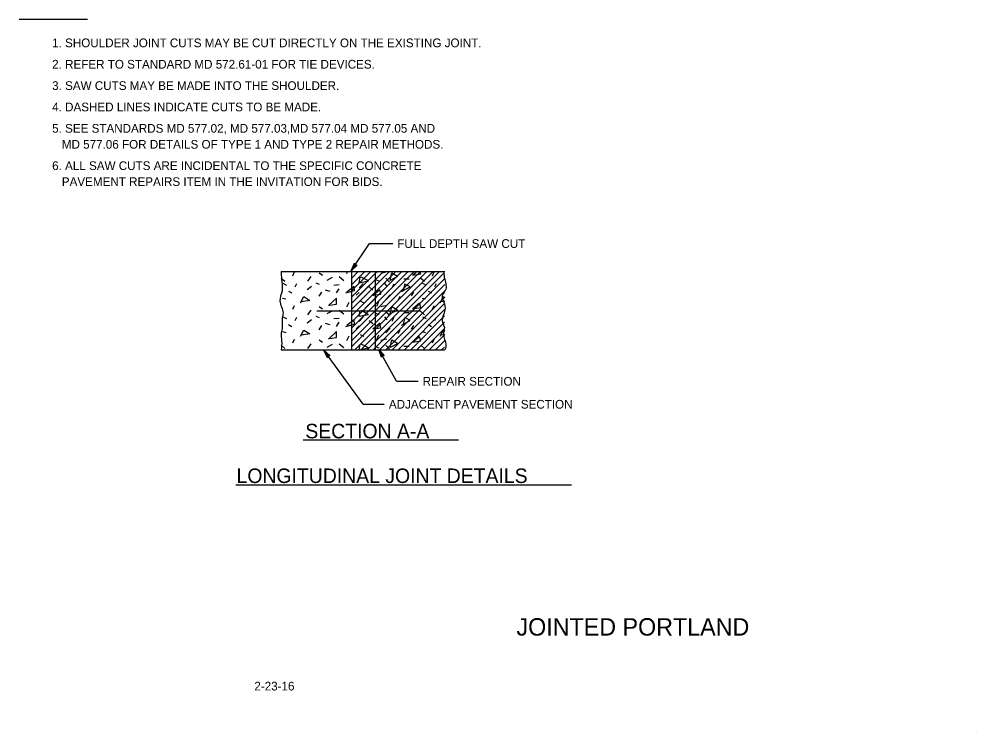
# Model space of a CAD drawing. Extents: x 1.45 to 8.06, y 0.17 to 9.98.
# Drawn here: x 1.45 to 8.06, y 0.17 to 5.09 of the extents above; entities that cross this region are included whole.
import ezdxf

# ---------------------------------------------------------------- set-up
doc = ezdxf.new("R2010")
doc.units = 0
for name, color, linetype in [('DETL-DIMS', 7, 'Continuous'), ('DETL-LINE', 7, 'Continuous'), ('DETL-NOTE', 7, 'Continuous'), ('DETL-PATT', 7, 'Continuous'), ('DETL-TITL', 7, 'Continuous'), ('TTLB-TEXT', 7, 'Continuous')]:
    doc.layers.add(name, color=color, linetype=linetype)

msp = doc.modelspace()

# ---------------------------------------------------------------- linework, layer by layer
at = {"layer": 'DETL-DIMS'}
for p, q in [((3.7436, 3.3526), (3.8699, 3.5416)), ((3.8699, 3.5416), (4.0305, 3.5416)), ((3.9662, 3.5416), (4.0305, 3.5416)), ((3.8267, 2.4338), (3.5558, 2.8069)), ((3.8267, 2.4338), (3.5558, 2.8069)), ((4.0547, 2.5922), (3.934, 2.8122)), ((4.0547, 2.5922), (3.934, 2.8122)), ((4.0547, 2.5922), (4.2054, 2.5922)), ((3.8267, 2.4338), (3.9713, 2.4338))]:
    msp.add_line(p, q, dxfattribs=at)
for points in [[(3.7436, 3.3526), (3.7662, 3.4054), (3.7663, 3.4001), (3.7682, 3.3962), (3.771, 3.3935), (3.7745, 3.392), (3.7789, 3.3917), (3.7838, 3.3937), (3.7436, 3.3526), (3.7789, 3.3917), (3.7745, 3.392), (3.7436, 3.3526), (3.771, 3.3935), (3.7682, 3.3962), (3.7436, 3.3526), (3.7663, 3.4001)], [(3.5558, 2.8069), (3.5975, 2.7674), (3.5925, 2.7691), (3.5882, 2.7687), (3.5847, 2.767), (3.582, 2.7643), (3.5803, 2.7602), (3.5804, 2.7549), (3.5558, 2.8069), (3.5803, 2.7602), (3.582, 2.7643), (3.5558, 2.8069), (3.5847, 2.767), (3.5882, 2.7687), (3.5558, 2.8069), (3.5925, 2.7691)], [(3.5558, 2.8069), (3.5975, 2.7674), (3.5925, 2.7691), (3.5882, 2.7687), (3.5847, 2.767), (3.582, 2.7643), (3.5803, 2.7602), (3.5804, 2.7549), (3.5558, 2.8069), (3.5803, 2.7602), (3.582, 2.7643), (3.5558, 2.8069), (3.5847, 2.767), (3.5882, 2.7687), (3.5558, 2.8069), (3.5925, 2.7691)], [(3.5558, 2.8069), (3.5975, 2.7674), (3.5925, 2.7691), (3.5882, 2.7687), (3.5847, 2.767), (3.582, 2.7643), (3.5803, 2.7602), (3.5804, 2.7549), (3.5558, 2.8069), (3.5803, 2.7602), (3.582, 2.7643), (3.5558, 2.8069), (3.5847, 2.767), (3.5882, 2.7687), (3.5558, 2.8069), (3.5925, 2.7691)], [(3.5558, 2.8069), (3.5975, 2.7674), (3.5925, 2.7691), (3.5882, 2.7687), (3.5847, 2.767), (3.582, 2.7643), (3.5803, 2.7602), (3.5804, 2.7549), (3.5558, 2.8069), (3.5803, 2.7602), (3.582, 2.7643), (3.5558, 2.8069), (3.5847, 2.767), (3.5882, 2.7687), (3.5558, 2.8069), (3.5925, 2.7691)], [(3.5558, 2.8069), (3.5975, 2.7674), (3.5925, 2.7691), (3.5882, 2.7687), (3.5847, 2.767), (3.582, 2.7643), (3.5803, 2.7602), (3.5804, 2.7549), (3.5558, 2.8069), (3.5803, 2.7602), (3.582, 2.7643), (3.5558, 2.8069), (3.5847, 2.767), (3.5882, 2.7687), (3.5558, 2.8069), (3.5925, 2.7691)], [(3.934, 2.8122), (3.9704, 2.7678), (3.9657, 2.7702), (3.9613, 2.7703), (3.9577, 2.7691), (3.9547, 2.7667), (3.9524, 2.7629), (3.9519, 2.7576), (3.934, 2.8122), (3.9524, 2.7629), (3.9547, 2.7667), (3.934, 2.8122), (3.9577, 2.7691), (3.9613, 2.7703), (3.934, 2.8122), (3.9657, 2.7702)], [(3.934, 2.8122), (3.9704, 2.7678), (3.9657, 2.7702), (3.9613, 2.7703), (3.9577, 2.7691), (3.9547, 2.7667), (3.9524, 2.7629), (3.9519, 2.7576), (3.934, 2.8122), (3.9524, 2.7629), (3.9547, 2.7667), (3.934, 2.8122), (3.9577, 2.7691), (3.9613, 2.7703), (3.934, 2.8122), (3.9657, 2.7702)], [(3.934, 2.8122), (3.9704, 2.7678), (3.9657, 2.7702), (3.9613, 2.7703), (3.9577, 2.7691), (3.9547, 2.7667), (3.9524, 2.7629), (3.9519, 2.7576), (3.934, 2.8122), (3.9524, 2.7629), (3.9547, 2.7667), (3.934, 2.8122), (3.9577, 2.7691), (3.9613, 2.7703), (3.934, 2.8122), (3.9657, 2.7702)], [(3.934, 2.8122), (3.9704, 2.7678), (3.9657, 2.7702), (3.9613, 2.7703), (3.9577, 2.7691), (3.9547, 2.7667), (3.9524, 2.7629), (3.9519, 2.7576), (3.934, 2.8122), (3.9524, 2.7629), (3.9547, 2.7667), (3.934, 2.8122), (3.9577, 2.7691), (3.9613, 2.7703), (3.934, 2.8122), (3.9657, 2.7702)]]:
    msp.add_lwpolyline(points, dxfattribs=at)
at = {"layer": 'DETL-LINE'}
for p, q in [((3.2601, 3.3482), (4.38, 3.3482)), ((3.7447, 3.3471), (3.7447, 3.0778)), ((3.9082, 3.3482), (3.9082, 2.8084)), ((3.5059, 3.0778), (4.2241, 3.0778)), ((3.5059, 3.0778), (4.2241, 3.0778)), ((3.7447, 3.0778), (3.7447, 2.8084)), ((3.2601, 2.8084), (4.3638, 2.8084)), ((3.2601, 2.8084), (4.3638, 2.8084)), ((4.3552, 2.8084), (4.3898, 2.8084))]:
    msp.add_line(p, q, dxfattribs=at)
for points in [[(3.2601, 3.3482), (3.2639, 3.2962), (3.2666, 3.2165), (3.2517, 3.1462), (3.2733, 3.0638), (3.2679, 3.03), (3.2679, 2.9638), (3.2612, 2.926), (3.2639, 2.8706), (3.2601, 2.8084)], [(4.38, 3.3482), (4.3878, 3.2949), (4.3921, 3.2173), (4.3706, 3.1806), (4.3813, 3.1374), (4.39, 3.0814), (4.3706, 3.0123), (4.3857, 2.9627), (4.3792, 2.9152), (4.3964, 2.8462), (4.3898, 2.8084)]]:
    msp.add_spline(points, degree=3, dxfattribs=at)
at = {"layer": 'DETL-NOTE'}
msp.add_line((1.4545, 5.0884), (1.9256, 5.0884), dxfattribs=at)
at = {"layer": 'DETL-PATT'}
for p, q in [((3.2601, 3.3039), (3.2856, 3.2815)), ((3.3402, 3.32), (3.353, 3.3457)), ((3.4653, 3.3136), (3.4429, 3.2815)), ((3.5231, 3.3393), (3.5456, 3.3233)), ((3.613, 3.3072), (3.5745, 3.288)), ((3.6611, 3.3136), (3.6932, 3.288)), ((3.7125, 3.3361), (3.7185, 3.3482)), ((3.7439, 2.8283), (4.2611, 3.3455)), ((3.7439, 2.8283), (4.2611, 3.3455)), ((3.7447, 3.1719), (3.9201, 3.3473)), ((3.7447, 3.1291), (3.9627, 3.3471)), ((3.7447, 3.0862), (4.0053, 3.3468)), ((3.7447, 3.0433), (4.0479, 3.3466)), ((3.7447, 3.0005), (4.0906, 3.3464)), ((3.7447, 2.9576), (4.1332, 3.3462)), ((3.7449, 2.8721), (4.2185, 3.3457)), ((3.7449, 2.8721), (4.2185, 3.3457)), ((3.7452, 3.3439), (3.7495, 3.3482)), ((3.7452, 3.3439), (3.7495, 3.3482)), ((3.7452, 3.301), (3.7922, 3.348)), ((3.7452, 3.301), (3.7922, 3.348)), ((3.7452, 3.2582), (3.8348, 3.3477)), ((3.7452, 3.2582), (3.8348, 3.3477)), ((3.7452, 3.2153), (3.8774, 3.3475)), ((3.7452, 3.2153), (3.8774, 3.3475)), ((3.7458, 2.9159), (4.1758, 3.3459)), ((3.7458, 2.9159), (4.1758, 3.3459)), ((3.7568, 3.1841), (3.9201, 3.3473)), ((3.7698, 2.8113), (4.3037, 3.3453)), ((3.7698, 2.8113), (4.3037, 3.3453)), ((3.7856, 3.1699), (3.9627, 3.3471)), ((3.8124, 2.8111), (4.3464, 3.345)), ((3.8124, 2.8111), (4.3464, 3.345)), ((3.8143, 3.1558), (4.0053, 3.3468)), ((3.839, 3.1376), (4.0479, 3.3466)), ((3.8395, 3.0954), (4.0906, 3.3464)), ((3.8401, 3.0531), (4.1332, 3.3462)), ((3.8551, 2.8109), (4.3816, 3.3374)), ((3.8551, 2.8109), (4.3816, 3.3374)), ((3.8977, 2.8107), (4.3887, 3.3016)), ((3.8977, 2.8107), (4.3887, 3.3016)), ((3.9214, 3.3482), (3.9178, 3.3393)), ((3.9884, 3.3457), (3.9467, 3.3361)), ((3.982, 3.304), (4.0077, 3.2751)), ((4.2227, 3.304), (4.2484, 3.2815)), ((4.3029, 3.32), (4.3158, 3.3457)), ((4.3552, 3.3482), (4.3898, 3.3482)), ((4.3552, 3.3482), (4.3898, 3.3482)), ((3.2728, 3.2687), (3.2985, 3.2559)), ((3.3562, 3.243), (3.3691, 3.2655)), ((3.4686, 3.2462), (3.4397, 3.2238)), ((3.5006, 3.2719), (3.5231, 3.2623)), ((3.6226, 3.2559), (3.6611, 3.2591)), ((3.7991, 3.2366), (3.8248, 3.2655)), ((3.8665, 3.243), (3.8922, 3.2206)), ((3.9082, 3.2944), (3.9339, 3.2847)), ((3.9403, 2.8104), (4.3884, 3.2585)), ((3.9403, 2.8104), (4.3884, 3.2585)), ((3.9724, 3.2687), (3.9884, 3.2462)), ((4.0366, 3.2623), (4.0237, 3.2366)), ((4.1072, 3.2976), (4.1425, 3.2976)), ((4.2355, 3.2687), (4.2612, 3.2559)), ((4.319, 3.243), (4.3318, 3.2655)), ((3.3113, 3.2141), (3.3338, 3.2013)), ((3.5392, 3.2077), (3.5199, 3.1788)), ((3.5648, 3.2238), (3.5969, 3.2141)), ((3.6418, 3.2013), (3.6611, 3.2302)), ((3.7766, 3.1853), (3.7991, 3.2045)), ((4.0109, 3.1885), (3.982, 3.1564)), ((3.983, 2.8102), (4.3881, 3.2154)), ((3.983, 2.8102), (4.3881, 3.2154)), ((4.0256, 2.81), (4.3879, 3.1723)), ((4.0256, 2.81), (4.3879, 3.1723)), ((4.0783, 3.1756), (4.0655, 3.15)), ((4.1585, 3.182), (4.1746, 3.2077)), ((4.2741, 3.2141), (4.2965, 3.2013)), ((3.2696, 3.166), (3.292, 3.1596)), ((3.3402, 3.089), (3.353, 3.1147)), ((3.5231, 3.1082), (3.5456, 3.0922)), ((3.7125, 3.105), (3.7285, 3.1371)), ((3.8055, 3.1467), (3.8312, 3.1339)), ((3.9307, 3.1403), (3.9178, 3.1082)), ((3.9884, 3.1147), (3.9467, 3.105)), ((4.0682, 2.8098), (4.3836, 3.1252)), ((4.0682, 2.8098), (4.3836, 3.1252)), ((4.2323, 3.166), (4.2548, 3.1596)), ((4.3029, 3.089), (4.3158, 3.1147)), ((3.2728, 3.0376), (3.2985, 3.0248)), ((3.4653, 3.0826), (3.4429, 3.0505)), ((3.5006, 3.0408), (3.5231, 3.0312)), ((3.613, 3.0761), (3.5745, 3.0569)), ((3.6611, 3.0826), (3.6932, 3.0569)), ((3.9082, 3.0633), (3.9339, 3.0537)), ((3.9724, 3.0376), (3.9884, 3.0152)), ((3.982, 3.0729), (4.0077, 3.0441)), ((4.1072, 3.0665), (4.1425, 3.0665)), ((4.1108, 2.8095), (4.3873, 3.086)), ((4.1108, 2.8095), (4.3873, 3.086)), ((4.1535, 2.8093), (4.387, 3.0429)), ((4.1535, 2.8093), (4.387, 3.0429)), ((4.2227, 3.0729), (4.2484, 3.0505)), ((4.2355, 3.0376), (4.2612, 3.0248)), ((3.3113, 2.9831), (3.3338, 2.9702)), ((3.3562, 3.012), (3.3691, 3.0344)), ((3.4686, 3.0152), (3.4397, 2.9927)), ((3.5392, 2.9767), (3.5199, 2.9478)), ((3.5648, 2.9927), (3.5969, 2.9831)), ((3.6226, 3.0248), (3.6611, 3.028)), ((3.6418, 2.9702), (3.6611, 2.9991)), ((3.7468, 2.9598), (3.7618, 2.9747)), ((3.7468, 2.9598), (3.7618, 2.9747)), ((3.7766, 2.9542), (3.7991, 2.9735)), ((3.7991, 3.0055), (3.8248, 3.0344)), ((3.8665, 3.012), (3.8922, 2.9895)), ((4.0366, 3.0312), (4.0237, 3.0055)), ((4.1585, 2.951), (4.1746, 2.9767)), ((4.1961, 2.8091), (4.3868, 2.9997)), ((4.1961, 2.8091), (4.3868, 2.9997)), ((4.2741, 2.9831), (4.2965, 2.9702)), ((4.319, 3.012), (4.3318, 3.0344)), ((3.2696, 2.9349), (3.292, 2.9285)), ((3.7125, 2.874), (3.7285, 2.9061)), ((3.8055, 2.9157), (3.8312, 2.9029)), ((3.9307, 2.9093), (3.9178, 2.8772)), ((4.0109, 2.9574), (3.982, 2.9253)), ((4.0783, 2.9446), (4.0655, 2.9189)), ((4.2323, 2.9349), (4.2548, 2.9285)), ((4.2387, 2.8089), (4.3865, 2.9566)), ((4.2387, 2.8089), (4.3865, 2.9566)), ((4.2814, 2.8086), (4.3862, 2.9135)), ((4.2814, 2.8086), (4.3862, 2.9135)), ((3.2601, 2.8418), (3.2856, 2.8194)), ((3.3402, 2.8579), (3.353, 2.8836)), ((3.4653, 2.8515), (3.4429, 2.8194)), ((3.5231, 2.8772), (3.5456, 2.8611)), ((3.613, 2.8451), (3.5745, 2.8258)), ((3.6611, 2.8515), (3.6932, 2.8258)), ((3.9884, 2.8836), (3.9467, 2.874)), ((3.982, 2.8419), (4.0077, 2.813)), ((4.2227, 2.8419), (4.2484, 2.8194)), ((4.3029, 2.8579), (4.3158, 2.8836)), ((4.324, 2.8084), (4.3859, 2.8704)), ((4.324, 2.8084), (4.3859, 2.8704)), ((3.5006, 2.8098), (3.5038, 2.8084)), ((3.9082, 2.8323), (3.9339, 2.8226)), ((4.1072, 2.8355), (4.1425, 2.8355)), ((4.3552, 2.8084), (4.3898, 2.8084)), ((4.3666, 2.8082), (4.3857, 2.8272))]:
    msp.add_line(p, q, dxfattribs=at)
for points in [[(3.5899, 3.3482), (3.5873, 3.3457)], [(3.8023, 3.3104), (3.7959, 3.2719), (3.8633, 3.2847), (3.8119, 3.3104)], [(4.0622, 3.3136), (4.0109, 3.288), (4.0237, 3.3393), (4.0622, 3.3168)], [(4.1649, 3.3233), (4.2227, 3.3329), (4.2176, 3.3482)], [(4.1973, 3.3482), (4.1682, 3.3233)], [(3.706, 3.2013), (3.767, 3.2174), (3.7638, 3.2462), (3.7125, 3.2077)], [(4.0911, 3.2109), (4.1489, 3.243), (4.1136, 3.2623), (4.1008, 3.2174)], [(3.3947, 3.1339), (3.4172, 3.1756), (3.4589, 3.15), (3.4012, 3.1403)], [(3.8922, 3.1853), (3.9467, 3.1917), (3.9403, 3.2238), (3.8922, 3.182)], [(4.3575, 3.1339), (4.38, 3.1756), (4.3898, 3.1696)], [(3.5937, 3.1179), (3.6418, 3.1243), (3.6418, 3.166), (3.5873, 3.1147)], [(4.0622, 3.0826), (4.0109, 3.0569), (4.0237, 3.1082), (4.0622, 3.0858)], [(4.1649, 3.0922), (4.2227, 3.1018), (4.2131, 3.1307), (4.1682, 3.0922)], [(4.3898, 3.1446), (4.3639, 3.1403)], [(3.8023, 3.0794), (3.7959, 3.0408), (3.8633, 3.0537), (3.8119, 3.0794)], [(3.706, 2.9702), (3.767, 2.9863), (3.7638, 3.0152), (3.7125, 2.9767)], [(3.8922, 2.9542), (3.9467, 2.9606), (3.9403, 2.9927), (3.8922, 2.951)], [(4.0911, 2.9799), (4.1489, 3.012), (4.1136, 3.0312), (4.1008, 2.9863)], [(3.3947, 2.9029), (3.4172, 2.9446), (3.4589, 2.9189), (3.4012, 2.9093)], [(3.5937, 2.8868), (3.6418, 2.8932), (3.6418, 2.9349), (3.5873, 2.8836)], [(4.3575, 2.9029), (4.38, 2.9446), (4.3898, 2.9385)], [(4.3898, 2.9136), (4.3639, 2.9093)], [(3.8023, 2.8483), (3.7959, 2.8098), (3.8633, 2.8226), (3.8119, 2.8483)], [(4.0622, 2.8515), (4.0109, 2.8258), (4.0237, 2.8772), (4.0622, 2.8547)], [(4.1649, 2.8611), (4.2227, 2.8708), (4.2131, 2.8996), (4.1682, 2.8611)]]:
    msp.add_lwpolyline(points, dxfattribs=at)
at = {"layer": 'DETL-TITL'}
for p, q in [((4.4821, 2.1866), (3.4115, 2.1866)), ((4.4529, 2.1866), (3.4233, 2.1866)), ((2.9479, 1.8787), (5.2614, 1.8787)), ((2.9583, 1.8787), (5.2468, 1.8787))]:
    msp.add_line(p, q, dxfattribs=at)
at = {"layer": 'TTLB-TEXT'}
msp.add_line((8.0562, 0.1691), (8.0562, 0.1691), dxfattribs=at)

# ---------------------------------------------------------------- texts
at = {"layer": 'DETL-NOTE'}
for s, p in [('1. SHOULDER JOINT CUTS MAY BE CUT DIRECTLY ON THE EXISTING JOINT.', (1.6818, 4.8949)), ('2. REFER TO STANDARD MD 572.61-01 FOR TIE DEVICES.', (1.6818, 4.7476)), ('3. SAW CUTS MAY BE MADE INTO THE SHOULDER.', (1.6818, 4.6003)), ('4. DASHED LINES INDICATE CUTS TO BE MADE.', (1.6818, 4.453)), ('5. SEE STANDARDS MD 577.02, MD 577.03,MD 577.04 MD 577.05 AND', (1.6818, 4.3057)), ('   MD 577.06 FOR DETAILS OF TYPE 1 AND TYPE 2 REPAIR METHODS.', (1.6818, 4.1957)), ('6. ALL SAW CUTS ARE INCIDENTAL TO THE SPECIFIC CONCRETE', (1.6818, 4.0484)), ('   PAVEMENT REPAIRS ITEM IN THE INVITATION FOR BIDS.', (1.6818, 3.9384)), ('FULL DEPTH SAW CUT', (4.0608, 3.5116)), ('REPAIR SECTION', (4.2356, 2.5622)), ('ADJACENT PAVEMENT SECTION', (4.0031, 2.4038))]:
    msp.add_text(s, height=0.06, dxfattribs=at).set_placement(p)
at = {"layer": 'DETL-TITL'}
for s, p in [('SECTION A-A', (3.4274, 2.1991)), ('LONGITUDINAL JOINT DETAILS', (2.9532, 1.8912))]:
    msp.add_text(s, height=0.1, dxfattribs=at).set_placement(p)
at = {"layer": 'TTLB-TEXT'}
for s, height, p in [('JOINTED PORTLAND', 0.12, (4.8828, 0.8394)), ('2-23-16', 0.06, (3.0758, 0.4612))]:
    msp.add_text(s, height=height, dxfattribs=at).set_placement(p)

doc.saveas('drawing.dxf')
